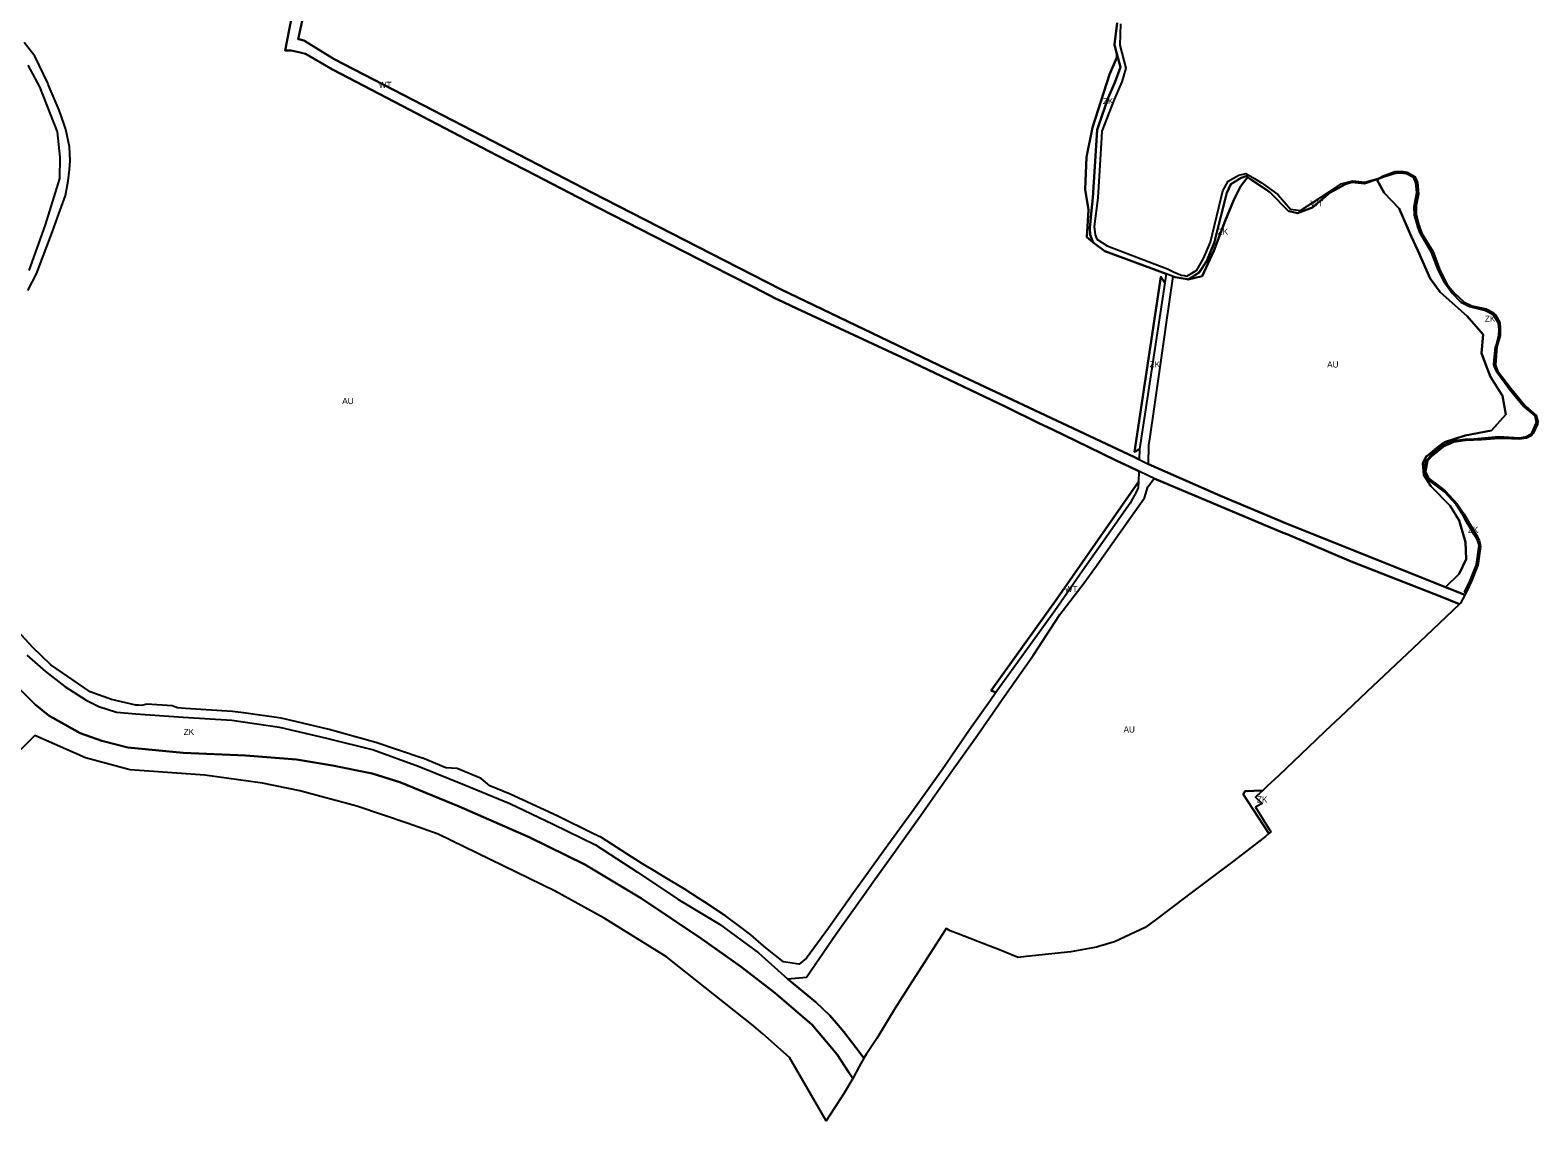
# Model space of a CAD drawing. Extents: x -545779 to -541342, y -1153413 to -1149956.
# Drawn here: x -542580 to -541342, y -1151576 to -1150681 of the extents above; entities that cross this region are included whole.
import ezdxf

# ---------------------------------------------------------------- set-up
doc = ezdxf.new("R2010")
doc.units = 0
for name, color, linetype in [('90640013', 7, 'Continuous'), ('90710013', 7, 'Continuous'), ('90750013', 7, 'Continuous')]:
    doc.layers.add(name, color=color, linetype=linetype)

msp = doc.modelspace()

# ---------------------------------------------------------------- linework, layer by layer
at = {"layer": '90640013'}
for points in [[(-542354.69, -1150664.61), (-542359.8, -1150688.41), (-542359.5, -1150688.49), (-542355.18, -1150689.58), (-542354.84, -1150689.67), (-542330.38, -1150704.75), (-542192.55, -1150776.06), (-542118.73, -1150814.37), (-541998.47, -1150875.88), (-541963.17, -1150894.02), (-541827.25, -1150959.17), (-541673.46, -1151031.35), (-541672.9, -1151031.63), (-541669.01, -1151033.55), (-541668.39, -1151033.85), (-541663.52, -1151036.25), (-541661.48, -1151037.26), (-541602.35, -1151063.41), (-541552.59, -1151084.23), (-541548.9, -1151085.78), (-541417.28, -1151138.39), (-541401.51, -1151144.66), (-541402.21, -1151146), (-541403.13, -1151147.78), (-541405.01, -1151151.39), (-541405.91, -1151152.25), (-541420.73, -1151146.35), (-541494.83, -1151117.22), (-541546.92, -1151095.23), (-541550.69, -1151093.64), (-541656.68, -1151049), (-541660.71, -1151047.14), (-541661.27, -1151046.88), (-541669.27, -1151043.18), (-541676.61, -1151039.66), (-541677.17, -1151039.39), (-541687.38, -1151034.5), (-541710.82, -1151023.16), (-541740.3, -1151008.9), (-541751.35, -1151003.55), (-541778.54, -1150990.41), (-541848.73, -1150956.79), (-541864.34, -1150949.52), (-541950.17, -1150909.55), (-541965.98, -1150902.18), (-541966.13, -1150902.11), (-541974.07, -1150898.02), (-541985.56, -1150892.13), (-542005.48, -1150881.94), (-542067.66, -1150850.1), (-542112.67, -1150827.06), (-542122.73, -1150821.92), (-542172.78, -1150796.01), (-542196.89, -1150783.53), (-542257.9, -1150751.81), (-542274.43, -1150743.21), (-542331.67, -1150713.45), (-542353.42, -1150700.71), (-542354, -1150700.56), (-542358.22, -1150699.49), (-542365.74, -1150697.59), (-542370.7, -1150697.82), (-542363.21, -1150659.75)], [(-541684.35, -1150675.91), (-541684.91, -1150693.21), (-541679.89, -1150712.34), (-541683.37, -1150723.57), (-541689.59, -1150737.85), (-541699.62, -1150763.88), (-541699.96, -1150769.23), (-541701.1, -1150787.3), (-541703.08, -1150818.57), (-541705.94, -1150842.11), (-541705.28, -1150849.04), (-541703.75, -1150852.54), (-541695.38, -1150858.04), (-541646.63, -1150876.57), (-541645.28, -1150877.21), (-541640.74, -1150879.36), (-541635.16, -1150882.01), (-541634.18, -1150882.17), (-541631.8, -1150882.54), (-541629.8, -1150882.86), (-541621.73, -1150877.97), (-541616.14, -1150868.62), (-541610.41, -1150855.21), (-541600.46, -1150813.05), (-541596.02, -1150804.9), (-541587.11, -1150799.97), (-541581.47, -1150798.58), (-541574.27, -1150802.94), (-541568.55, -1150806.41), (-541566.93, -1150807.39), (-541555.2, -1150816.02), (-541544.64, -1150827.92), (-541536.57, -1150829.13), (-541514.73, -1150814.75), (-541503.05, -1150807.29), (-541493.52, -1150804.67), (-541483.65, -1150805.93), (-541472.85, -1150802.8), (-541468.55, -1150800.67), (-541458.64, -1150797.05), (-541453.94, -1150796.84), (-541448.95, -1150797.56), (-541442.6, -1150801.14), (-541440.54, -1150805.98), (-541439.68, -1150815.7), (-541441.59, -1150825.09), (-541441.64, -1150832.17), (-541439.44, -1150840.72), (-541436.84, -1150847.86), (-541427.48, -1150862.99), (-541422.21, -1150877.34), (-541416.16, -1150889.72), (-541410.65, -1150896.52), (-541402.08, -1150904.44), (-541395.84, -1150907.27), (-541384.1, -1150909.84), (-541378.3, -1150912.89), (-541376.43, -1150914.8), (-541372.76, -1150920.99), (-541372.41, -1150925.96), (-541372.47, -1150931.81), (-541375.23, -1150940.99), (-541376.1, -1150951.86), (-541376.43, -1150956.01), (-541374.58, -1150960.81), (-541363.97, -1150974.8), (-541351.52, -1150989.94), (-541342.82, -1150997.46), (-541341.55, -1151002.4), (-541341.81, -1151004.38), (-541345.44, -1151012.04), (-541346.91, -1151014.2), (-541350.83, -1151015.99), (-541356.72, -1151016.87), (-541369.85, -1151016.37), (-541373.79, -1151016.22), (-541377.23, -1151016.48), (-541387.94, -1151017.31), (-541401.02, -1151017.95), (-541410.45, -1151019.19), (-541419.27, -1151023.23), (-541428.14, -1151030.35), (-541432.16, -1151034.6), (-541433.82, -1151043.57), (-541431.5, -1151048.8), (-541427.7, -1151051.65), (-541425.77, -1151053.08), (-541417.67, -1151059.15), (-541408.15, -1151069.66), (-541401.94, -1151078.38), (-541398.85, -1151084.04), (-541391.25, -1151097.01), (-541389.7, -1151099.65), (-541388.89, -1151103.33), (-541388.56, -1151104.83), (-541390.78, -1151120.55), (-541391.27, -1151121.74), (-541396.1, -1151133.41), (-541400.46, -1151142.64), (-541401.75, -1151142.23), (-541397.09, -1151132.98), (-541392.19, -1151120.64), (-541391.86, -1151119.82), (-541389.67, -1151103.99), (-541391.19, -1151099.55), (-541392.5, -1151097.37), (-541393.76, -1151095.29), (-541398.06, -1151088.14), (-541400.14, -1151084.69), (-541403.13, -1151078.94), (-541408.74, -1151070.35), (-541418.29, -1151059.99), (-541432.37, -1151049.31), (-541435.48, -1151042.81), (-541433.91, -1151037.21), (-541433.44, -1151035.51), (-541433.07, -1151034.18), (-541432.03, -1151033.06), (-541429.63, -1151030.46), (-541419.72, -1151022.12), (-541410.82, -1151018.06), (-541405.63, -1151017.6), (-541401.14, -1151017.2), (-541393.97, -1151016.74), (-541388.07, -1151016.37), (-541373.71, -1151014.99), (-541356.94, -1151015.99), (-541353.65, -1151015.32), (-541351.23, -1151014.83), (-541347.65, -1151013.07), (-541347.19, -1151012.84), (-541346.63, -1151012.56), (-541342.56, -1151003.19), (-541343.88, -1150997.71), (-541353.44, -1150989.7), (-541358.76, -1150983.18), (-541365.03, -1150975.49), (-541365.35, -1150975.05), (-541375.24, -1150961.48), (-541376.2, -1150959.31), (-541377.09, -1150957.28), (-541377.61, -1150956.1), (-541377.57, -1150954.85), (-541377.49, -1150952.12), (-541376.54, -1150943.8), (-541376.26, -1150941.37), (-541375.9, -1150940.13), (-541373.47, -1150931.65), (-541373.41, -1150926.78), (-541373.79, -1150921.5), (-541378.29, -1150914.37), (-541384.55, -1150911.1), (-541397.81, -1150907.95), (-541404.73, -1150904.46), (-541411.54, -1150897.22), (-541417.88, -1150888.6), (-541423.36, -1150877.83), (-541428.8, -1150863.56), (-541438.55, -1150847.09), (-541440.48, -1150841.58), (-541440.78, -1150840.4), (-541442.74, -1150832.79), (-541443.15, -1150826.13), (-541440.99, -1150814.25), (-541441.71, -1150806.31), (-541443.64, -1150801.61), (-541449.46, -1150798.82), (-541454.3, -1150798.1), (-541457.8, -1150798.38), (-541460.31, -1150799.09), (-541468.4, -1150801.39), (-541473.79, -1150803.58), (-541475.11, -1150804.01), (-541484.02, -1150806.94), (-541494.31, -1150805.9), (-541499.64, -1150807.59), (-541502.47, -1150809.13), (-541512.21, -1150814.4), (-541526.62, -1150826.74), (-541539.06, -1150831.21), (-541543.66, -1150830.15), (-541546.42, -1150829.51), (-541561.2, -1150814.46), (-541564.58, -1150812.19), (-541577.22, -1150803.68), (-541580.39, -1150801.54), (-541581.52, -1150800.78), (-541585.4, -1150802.39), (-541593.83, -1150807.34), (-541596.97, -1150814.71), (-541607.47, -1150855.63), (-541613.56, -1150870.48), (-541619.66, -1150879.97), (-541628.75, -1150885.66), (-541629.66, -1150885.51), (-541639.48, -1150883.94), (-541641.02, -1150883.33), (-541646.75, -1150881.02), (-541697.14, -1150862.37), (-541706.72, -1150855.22), (-541709.28, -1150848.94), (-541709.66, -1150843.58), (-541708.17, -1150829.2), (-541707.08, -1150818.67), (-541703.62, -1150762.82), (-541702.51, -1150759.64), (-541694.49, -1150736.66), (-541689, -1150724.04), (-541684.34, -1150711.48), (-541687.42, -1150700.33), (-541689.12, -1150694.15), (-541689.33, -1150693.39), (-541689.22, -1150692.46), (-541688.75, -1150688.41), (-541687.19, -1150674.93)], [(-542599.21, -1151211.3), (-542576.07, -1151234.58), (-542564.53, -1151243.99), (-542561.5, -1151245.67), (-542539.1, -1151258.11), (-542521.28, -1151264.58), (-542499.92, -1151269.95), (-542454.48, -1151274.26), (-542403.1, -1151276.5), (-542361.22, -1151279.86), (-542331.67, -1151284.76), (-542299.23, -1151291.36), (-542276.39, -1151298.44), (-542227.52, -1151318.28), (-542170.24, -1151343.71), (-542124.52, -1151366.15), (-542077.75, -1151393.85), (-542028.95, -1151426.86), (-541996.12, -1151450.12), (-541968.36, -1151471.37), (-541937.64, -1151497.73), (-541917.14, -1151522.01), (-541907.62, -1151536.71), (-541904.34, -1151541.77), (-541911.83, -1151554.71), (-541926.26, -1151576.49), (-541956.17, -1151524.36), (-541978.14, -1151505.15), (-541985.8, -1151498.46), (-542057.28, -1151441.71), (-542108.58, -1151410.14), (-542148.68, -1151388.03), (-542244.89, -1151341.18), (-542269.57, -1151332.27), (-542311.73, -1151318.19), (-542358.55, -1151305.44), (-542389.32, -1151299.21), (-542436.47, -1151292.57), (-542497.83, -1151288.4), (-542500, -1151287.82), (-542534.71, -1151278.57), (-542576.24, -1151260.17), (-542599.22, -1151282.78)]]:
    msp.add_lwpolyline(points, dxfattribs=at)
msp.add_lwpolyline([(-541736.32, -1151147.65), (-541669.73, -1151051.8), (-541669.99, -1151056.64), (-541670.97, -1151059.35), (-541676.45, -1151069.39), (-541692.5, -1151092.27), (-541715.58, -1151124.94), (-541738.26, -1151157.89), (-541761.76, -1151190.27), (-541786.85, -1151224.91), (-541790.54, -1151223.2)], close=True, dxfattribs=at)
at = {"layer": '90710013'}
for points in [[(-541713.34, -1150811.71), (-541712.37, -1150785.34), (-541707.34, -1150760.81), (-541693.39, -1150717.33), (-541687.35, -1150703.33), (-541687.42, -1150700.33), (-541684.34, -1150711.48), (-541689, -1150724.04), (-541694.49, -1150736.66), (-541702.51, -1150759.64), (-541703.62, -1150762.82), (-541707.08, -1150818.67), (-541708.17, -1150829.2), (-541709.66, -1150843.58), (-541709.28, -1150848.94), (-541706.72, -1150855.22), (-541711.94, -1150850.9), (-541710.56, -1150828.57)], [(-541607.47, -1150855.63), (-541596.97, -1150814.71), (-541593.83, -1150807.34), (-541585.4, -1150802.39), (-541581.52, -1150800.78), (-541580.39, -1150801.54), (-541580.28, -1150802.31), (-541582.13, -1150804.69), (-541585.75, -1150809.37), (-541591.34, -1150820.42), (-541598.3, -1150837.49), (-541607.81, -1150862.32), (-541617.26, -1150882.92), (-541623.18, -1150884.33), (-541628.75, -1150885.66), (-541619.66, -1150879.97), (-541613.56, -1150870.48)], [(-541455.56, -1150827.43), (-541467.69, -1150814.6), (-541473.79, -1150803.58), (-541468.4, -1150801.39), (-541460.31, -1150799.09), (-541457.8, -1150798.38), (-541454.3, -1150798.1), (-541449.46, -1150798.82), (-541443.64, -1150801.61), (-541441.71, -1150806.31), (-541440.99, -1150814.25), (-541443.15, -1150826.13), (-541442.74, -1150832.79), (-541440.78, -1150840.4), (-541440.48, -1150841.58), (-541438.55, -1150847.09), (-541428.8, -1150863.56), (-541423.36, -1150877.83), (-541417.88, -1150888.6), (-541411.54, -1150897.22), (-541404.73, -1150904.46), (-541397.81, -1150907.95), (-541384.55, -1150911.1), (-541378.29, -1150914.37), (-541373.79, -1150921.5), (-541373.41, -1150926.78), (-541373.47, -1150931.65), (-541375.9, -1150940.13), (-541376.26, -1150941.37), (-541376.54, -1150943.8), (-541377.49, -1150952.12), (-541377.57, -1150954.85), (-541377.61, -1150956.1), (-541377.09, -1150957.28), (-541376.2, -1150959.31), (-541375.24, -1150961.48), (-541365.35, -1150975.05), (-541365.03, -1150975.49), (-541358.76, -1150983.18), (-541353.44, -1150989.7), (-541343.88, -1150997.71), (-541342.56, -1151003.19), (-541346.63, -1151012.56), (-541347.19, -1151012.84), (-541347.65, -1151013.07), (-541351.23, -1151014.83), (-541353.65, -1151015.32), (-541356.94, -1151015.99), (-541373.71, -1151014.99), (-541388.07, -1151016.37), (-541393.97, -1151016.74), (-541401.14, -1151017.2), (-541405.63, -1151017.6), (-541410.82, -1151018.06), (-541419.72, -1151022.12), (-541429.63, -1151030.46), (-541432.03, -1151033.06), (-541433.07, -1151034.18), (-541433.44, -1151035.51), (-541433.91, -1151037.21), (-541435.48, -1151042.81), (-541435.96, -1151036.81), (-541433.17, -1151031.03), (-541431.51, -1151029.65), (-541423.13, -1151022.71), (-541418.1, -1151019.37), (-541401.14, -1151013.94), (-541379.7, -1151009.82), (-541367.75, -1150996.46), (-541370.66, -1150981.24), (-541380.41, -1150965.52), (-541384.23, -1150955.76), (-541387.96, -1150946.2), (-541386.6, -1150930.89), (-541399.6, -1150915.89), (-541421.73, -1150896.23), (-541430.1, -1150884.9), (-541440.22, -1150862.04), (-541445.54, -1150850.03)], [(-541673.02, -1151027.14), (-541651.19, -1150883.61), (-541647.9, -1150888.57), (-541668.65, -1151025.03)], [(-541401.03, -1151101.32), (-541405.38, -1151086.21), (-541406.09, -1151083.72), (-541413.59, -1151071.5), (-541429.54, -1151055.51), (-541435.21, -1151046.27), (-541435.48, -1151042.81), (-541432.37, -1151049.31), (-541418.29, -1151059.99), (-541408.74, -1151070.35), (-541403.13, -1151078.94), (-541400.14, -1151084.69), (-541398.06, -1151088.14), (-541393.76, -1151095.29), (-541392.5, -1151097.37), (-541391.19, -1151099.55), (-541389.67, -1151103.99), (-541391.86, -1151119.82), (-541392.19, -1151120.64), (-541397.09, -1151132.98), (-541401.75, -1151142.23), (-541400.46, -1151142.64), (-541401.51, -1151144.66), (-541417.28, -1151138.39), (-541406.25, -1151127.29), (-541400.45, -1151115.24)], [(-541562.48, -1151340.58), (-541583.6, -1151308.28), (-541582.01, -1151305.76), (-541567.57, -1151305.32), (-541570.4, -1151308), (-541571.56, -1151308.9), (-541573.46, -1151310.88), (-541568.08, -1151315.96), (-541569.18, -1151316.59), (-541573.4, -1151319), (-541560.96, -1151339.24)]]:
    msp.add_lwpolyline(points, close=True, dxfattribs=at)
for points in [[(-542581.97, -1150709.69), (-542572.32, -1150727.63), (-542558.01, -1150764.47), (-542555.82, -1150785.27), (-542555.97, -1150802.94), (-542567.63, -1150840.97), (-542581.09, -1150878.47)], [(-542582.93, -1151194.04), (-542567.35, -1151207.59), (-542551.48, -1151219.99), (-542533.99, -1151231.03), (-542523.59, -1151236.28), (-542509.26, -1151240.97), (-542493.4, -1151242.2), (-542454.35, -1151245.05), (-542414.44, -1151247.65), (-542375.15, -1151253.34), (-542336.56, -1151262.44), (-542298.1, -1151271.97), (-542260.39, -1151285.52), (-542223.21, -1151300.54), (-542186.05, -1151315.9), (-542150.34, -1151332.95), (-542115.64, -1151349.77), (-542081.19, -1151372.27), (-542047.95, -1151394.57), (-542013.91, -1151415.08), (-541981.87, -1151438.63), (-541957.83, -1151459.78), (-541934.74, -1151478.98), (-541923.16, -1151490.05), (-541917.79, -1151496.29), (-541911.74, -1151503.32), (-541898.27, -1151520.86), (-541895.31, -1151525.14), (-541898.94, -1151531.84), (-541904.34, -1151541.77), (-541907.62, -1151536.71), (-541917.14, -1151522.01), (-541937.64, -1151497.73), (-541968.36, -1151471.37), (-541996.12, -1151450.12), (-542028.95, -1151426.86), (-542077.75, -1151393.85), (-542124.52, -1151366.15), (-542170.24, -1151343.71), (-542227.52, -1151318.28), (-542276.39, -1151298.44), (-542299.23, -1151291.36), (-542331.67, -1151284.76), (-542361.22, -1151279.86), (-542403.1, -1151276.5), (-542454.48, -1151274.26), (-542499.92, -1151269.95), (-542521.28, -1151264.58), (-542539.1, -1151258.11), (-542561.5, -1151245.67), (-542564.53, -1151243.99), (-542576.07, -1151234.58), (-542599.21, -1151211.3)]]:
    msp.add_lwpolyline(points, dxfattribs=at)
at = {"layer": '90750013'}
for points in [[(-542363.21, -1150659.75), (-542370.7, -1150697.82), (-542365.74, -1150697.59), (-542358.22, -1150699.49), (-542354, -1150700.56), (-542353.42, -1150700.71), (-542331.67, -1150713.45), (-542274.43, -1150743.21), (-542257.9, -1150751.81), (-542196.89, -1150783.53), (-542172.78, -1150796.01), (-542122.73, -1150821.92), (-542112.67, -1150827.06), (-542067.66, -1150850.1), (-542005.48, -1150881.94), (-541985.56, -1150892.13), (-541974.07, -1150898.02), (-541966.13, -1150902.11), (-541965.98, -1150902.18), (-541950.17, -1150909.55), (-541864.34, -1150949.52), (-541848.73, -1150956.79), (-541778.54, -1150990.41), (-541751.35, -1151003.55), (-541740.3, -1151008.9), (-541710.82, -1151023.16), (-541687.38, -1151034.5), (-541677.17, -1151039.39), (-541676.61, -1151039.66), (-541669.27, -1151043.18), (-541669.73, -1151051.8), (-541736.32, -1151147.65), (-541790.54, -1151223.2), (-541786.85, -1151224.91), (-541791.57, -1151231.58), (-541808.38, -1151255.34), (-541830.92, -1151288.3), (-541854.18, -1151320.85), (-541877.84, -1151353.1), (-541896.65, -1151379.42), (-541903.66, -1151389.23), (-541924.36, -1151418.19), (-541942.23, -1151442.95), (-541948.26, -1151447.8), (-541950.44, -1151447.49), (-541961.19, -1151445.94), (-541974.31, -1151435.66), (-541977.44, -1151433.21), (-541988.12, -1151423.85), (-541996.09, -1151417.86), (-542009, -1151408.15), (-542025.97, -1151397.03), (-542031.13, -1151393.64), (-542042.69, -1151386.07), (-542059.67, -1151375.86), (-542065.61, -1151372.29), (-542076.98, -1151365.47), (-542085.96, -1151359.75), (-542110.8, -1151343.92), (-542117.23, -1151340.78), (-542147.18, -1151326.15), (-542185.87, -1151308.4), (-542202.53, -1151301.51), (-542209.71, -1151295.3), (-542229.24, -1151287.23), (-542238.72, -1151286.57), (-542257.64, -1151278.76), (-542257.96, -1151278.65), (-542295.99, -1151265.81), (-542334.58, -1151255.2), (-542362.09, -1151248.73), (-542373.91, -1151245.95), (-542404.95, -1151241.63), (-542413.96, -1151240.37), (-542452.78, -1151237.84), (-542459.17, -1151237.41), (-542463.53, -1151235.63), (-542484.13, -1151234.29), (-542488.5, -1151235.44), (-542491.06, -1151235.26), (-542493.28, -1151235.11), (-542513.28, -1151230.63), (-542530.65, -1151224.32), (-542562.98, -1151202.13), (-542578.28, -1151187.68), (-542590.02, -1151174.76)], [(-541687.19, -1150674.93), (-541688.75, -1150688.41), (-541689.22, -1150692.46), (-541689.33, -1150693.39), (-541689.12, -1150694.15), (-541687.42, -1150700.33), (-541687.35, -1150703.33), (-541693.39, -1150717.33), (-541707.34, -1150760.81), (-541712.37, -1150785.34), (-541713.34, -1150811.71), (-541710.56, -1150828.57), (-541711.94, -1150850.9), (-541706.72, -1150855.22), (-541697.14, -1150862.37), (-541646.75, -1150881.02), (-541647.9, -1150888.57), (-541651.19, -1150883.61), (-541673.02, -1151027.14), (-541668.65, -1151025.03), (-541669.01, -1151033.55), (-541672.9, -1151031.63), (-541673.46, -1151031.35), (-541827.25, -1150959.17), (-541963.17, -1150894.02), (-541998.47, -1150875.88), (-542118.73, -1150814.37), (-542192.55, -1150776.06), (-542330.38, -1150704.75), (-542354.84, -1150689.67), (-542355.18, -1150689.58), (-542359.5, -1150688.49), (-542359.8, -1150688.41), (-542354.69, -1150664.61)], [(-542581.96, -1150894.8), (-542574.79, -1150881.02), (-542561.62, -1150846.28), (-542557.56, -1150834.96), (-542551.16, -1150816.8), (-542548.81, -1150804.8), (-542547.89, -1150795.48), (-542547.18, -1150788.22), (-542547.73, -1150776.78), (-542550.87, -1150762.55), (-542552.24, -1150758.4), (-542556.14, -1150746.63), (-542565.25, -1150725.57), (-542565.68, -1150724.59), (-542576.23, -1150702.32), (-542585.01, -1150691.28)]]:
    msp.add_lwpolyline(points, dxfattribs=at)
for points in [[(-541552.59, -1151084.23), (-541602.35, -1151063.41), (-541661.48, -1151037.26), (-541661.12, -1151021.77), (-541660.1, -1151014.78), (-541656.81, -1150992.09), (-541647.91, -1150930.78), (-541646.75, -1150922.85), (-541641.02, -1150883.33), (-541639.48, -1150883.94), (-541629.66, -1150885.51), (-541628.75, -1150885.66), (-541623.18, -1150884.33), (-541617.26, -1150882.92), (-541607.81, -1150862.32), (-541598.3, -1150837.49), (-541591.34, -1150820.42), (-541585.75, -1150809.37), (-541582.13, -1150804.69), (-541580.28, -1150802.31), (-541580.39, -1150801.54), (-541577.22, -1150803.68), (-541564.58, -1150812.19), (-541561.2, -1150814.46), (-541546.42, -1150829.51), (-541543.66, -1150830.15), (-541539.06, -1150831.21), (-541526.62, -1150826.74), (-541512.21, -1150814.4), (-541502.47, -1150809.13), (-541499.64, -1150807.59), (-541494.31, -1150805.9), (-541484.02, -1150806.94), (-541475.11, -1150804.01), (-541473.79, -1150803.58), (-541467.69, -1150814.6), (-541455.56, -1150827.43), (-541445.54, -1150850.03), (-541440.22, -1150862.04), (-541430.1, -1150884.9), (-541421.73, -1150896.23), (-541399.6, -1150915.89), (-541386.6, -1150930.89), (-541387.96, -1150946.2), (-541384.23, -1150955.76), (-541380.41, -1150965.52), (-541370.66, -1150981.24), (-541367.75, -1150996.46), (-541379.7, -1151009.82), (-541401.14, -1151013.94), (-541418.1, -1151019.37), (-541423.13, -1151022.71), (-541431.51, -1151029.65), (-541433.17, -1151031.03), (-541435.96, -1151036.81), (-541435.48, -1151042.81), (-541435.21, -1151046.27), (-541429.54, -1151055.51), (-541413.59, -1151071.5), (-541406.09, -1151083.72), (-541405.38, -1151086.21), (-541401.03, -1151101.32), (-541400.45, -1151115.24), (-541406.25, -1151127.29), (-541417.28, -1151138.39), (-541548.9, -1151085.78)], [(-541892.29, -1151520.45), (-541892.98, -1151521.47), (-541895.31, -1151525.14), (-541898.27, -1151520.86), (-541911.74, -1151503.32), (-541917.79, -1151496.29), (-541923.16, -1151490.05), (-541934.74, -1151478.98), (-541957.83, -1151459.78), (-541942.36, -1151458.56), (-541917.85, -1151422.84), (-541894.59, -1151390.3), (-541887.49, -1151380.36), (-541871.34, -1151357.75), (-541848.08, -1151325.21), (-541825.23, -1151292.37), (-541801.79, -1151259.87), (-541784.65, -1151234.99), (-541777.76, -1151225.04), (-541756.04, -1151194.31), (-541734.18, -1151160.78), (-541714.29, -1151134.76), (-541703.6, -1151120.1), (-541693.08, -1151105.23), (-541680.57, -1151087.45), (-541664.81, -1151064.98), (-541661.92, -1151056.06), (-541656.68, -1151049), (-541550.69, -1151093.64), (-541546.92, -1151095.23), (-541494.83, -1151117.22), (-541420.73, -1151146.35), (-541405.91, -1151152.25), (-541444.34, -1151188.63), (-541482.08, -1151224.37), (-541499.04, -1151240.43), (-541504.06, -1151245.18), (-541515.91, -1151256.41), (-541523.92, -1151263.99), (-541554.44, -1151292.89), (-541563.88, -1151301.83), (-541567.57, -1151305.32), (-541582.01, -1151305.76), (-541583.6, -1151308.28), (-541562.48, -1151340.58), (-541565.25, -1151343.02), (-541566.33, -1151343.84), (-541592.42, -1151363.73), (-541626.35, -1151389.27), (-541654.93, -1151410.97), (-541664.04, -1151417.75), (-541689.44, -1151429.54), (-541702.37, -1151433.43), (-541704.18, -1151433.97), (-541725.25, -1151437.72), (-541761.92, -1151441.67), (-541768.33, -1151442.36), (-541785.23, -1151435.66), (-541791.85, -1151433.04), (-541817.7, -1151423.01), (-541824.24, -1151420.44), (-541827.61, -1151418.62), (-541828.93, -1151420.69), (-541857.45, -1151465.1), (-541869.63, -1151483.93), (-541884.69, -1151508.78), (-541889.39, -1151516.15)]]:
    msp.add_lwpolyline(points, close=True, dxfattribs=at)

# ---------------------------------------------------------------- texts
at = {"layer": '90640013'}
for rotation, p in [(0, (-542293.723, -1150728.436)), (360, (-541528.38, -1150825.698)), (360, (-541730.135, -1151142.417))]:
    msp.add_text('WT', height=5, rotation=rotation, dxfattribs=at).set_placement(p)
at = {"layer": '90710013'}
for rotation, p in [(360, (-541698.84, -1150741.721)), (0, (-541604.515, -1150848.915)), (0, (-541385.047, -1150920.455)), (360, (-541660.46, -1150957.864)), (0, (-541398.954, -1151093.735)), (0, (-542453.925, -1151259.681)), (0, (-541572.28, -1151315.177))]:
    msp.add_text('ZK', height=5, rotation=rotation, dxfattribs=at).set_placement(p)
at = {"layer": '90750013'}
for rotation, p in [(0, (-541514.615, -1150957.972)), (360, (-542323.66, -1150987.908)), (360, (-541681.87, -1151257.662))]:
    msp.add_text('AU', height=5, rotation=rotation, dxfattribs=at).set_placement(p)

doc.saveas('drawing.dxf')
